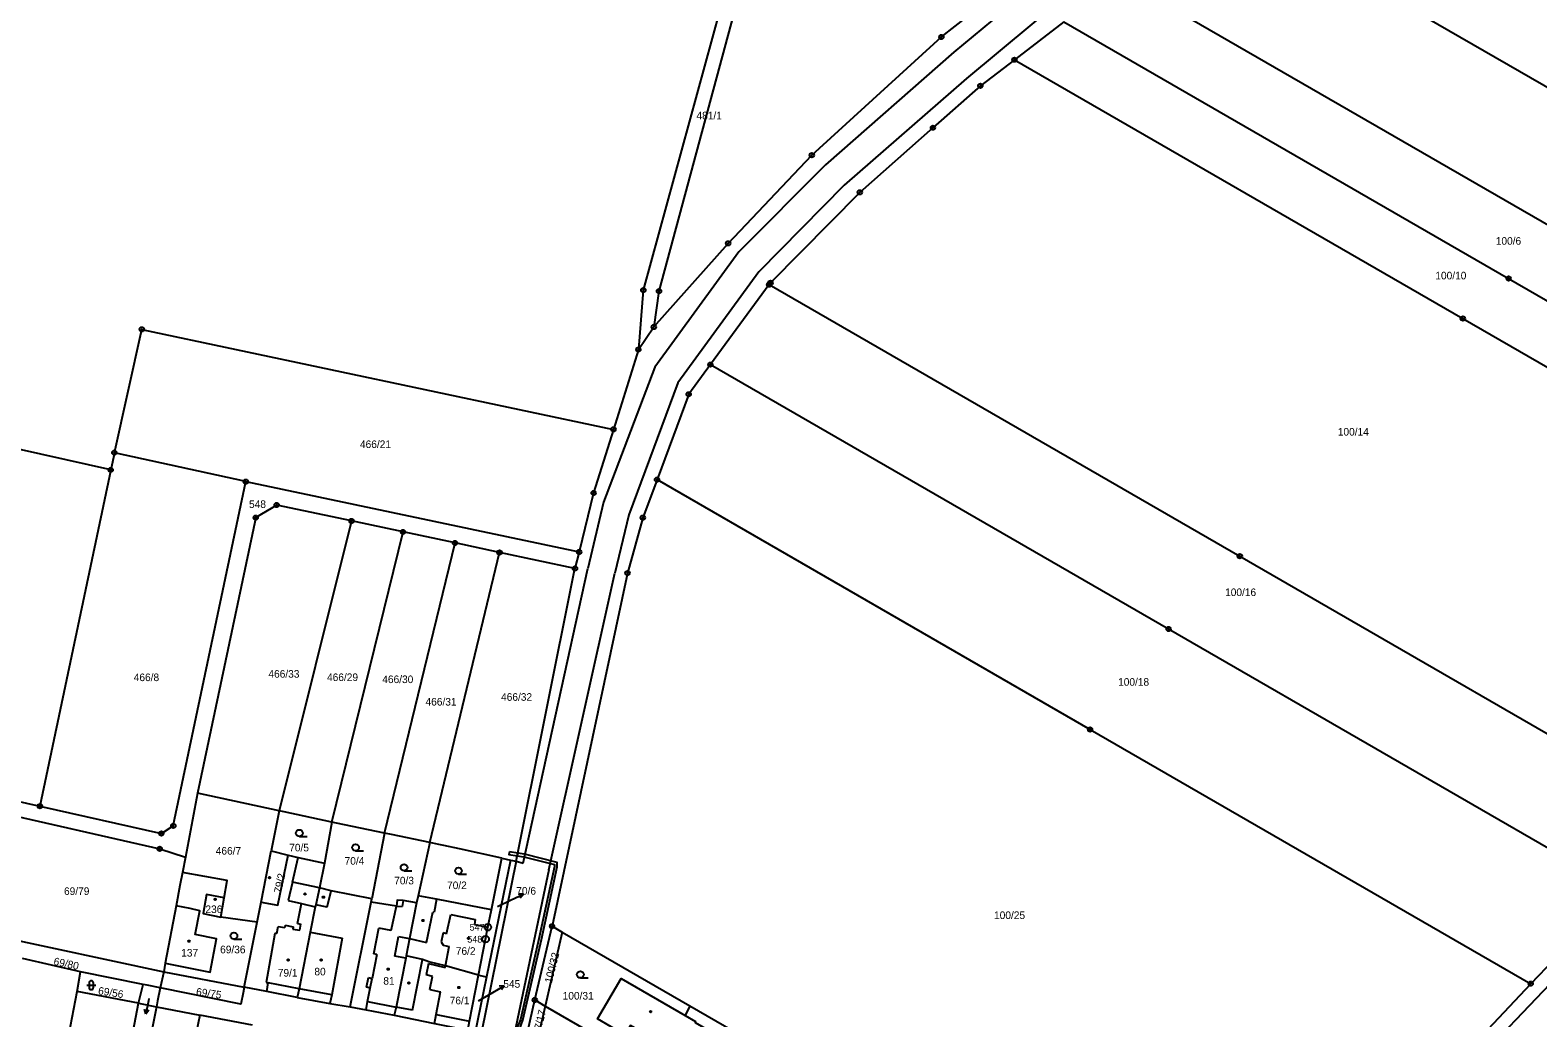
# Model space of a CAD drawing. Extents: x -758582 to -751794, y -998770 to -994350.
# Drawn here: x -756555.4 to -756217.6, y -996694.2 to -996472.9 of the extents above; entities that cross this region are included whole.
import ezdxf

# ---------------------------------------------------------------- set-up
doc = ezdxf.new("R2010")
doc.units = 0
for name, color, linetype in [('Hranice parcel', 7, 'Continuous'), ('Parcelní čísla', 7, 'Continuous'), ('Pop  PČ popisy', 7, 'Continuous'), ('Vnitřní kresba', 7, 'Continuous'), ('Věcná břemena k části', 7, 'Continuous'), ('Značky bodu BP', 7, 'Continuous'), ('Značky budov', 7, 'Continuous'), ('Značky kultur', 7, 'Continuous')]:
    doc.layers.add(name, color=color, linetype=linetype)

msp = doc.modelspace()

# ---------------------------------------------------------------- linework, layer by layer
at = {"layer": 'Hranice parcel'}
for p, q in [((-756323.8, -996471.09), (-756334.9, -996479.57)), ((-756389.84, -996529.96), (-756403, -996547.87)), ((-756419.13, -996544.5), (-756415.69, -996539.44)), ((-756419.13, -996544.5), (-756424.72, -996562.38)), ((-756537.34, -996571.47), (-756637.67, -996548.94)), ((-756536.53, -996567.61), (-756537.34, -996571.47)), ((-756507.07, -996574.09), (-756536.53, -996567.61)), ((-756537.34, -996571.47), (-756553.21, -996646.8)), ((-756507.07, -996574.09), (-756432.41, -996589.85)), ((-756483.39, -996582.91), (-756499.58, -996647.83)), ((-756471.85, -996585.36), (-756483.39, -996582.91)), ((-756487.79, -996650.37), (-756471.85, -996585.36)), ((-756476, -996652.82), (-756460.21, -996587.84)), ((-756460.21, -996587.84), (-756471.85, -996585.36)), ((-756450.24, -996589.96), (-756460.21, -996587.84)), ((-756465.85, -996654.97), (-756450.24, -996589.96)), ((-756433.34, -996593.55), (-756450.24, -996589.96)), ((-756432.41, -996589.85), (-756433.34, -996593.55)), ((-756517.93, -996643.88), (-756520.63, -996658.26)), ((-756499.58, -996647.83), (-756517.93, -996643.88)), ((-756499.58, -996647.83), (-756501.39, -996656.8)), ((-756487.79, -996650.37), (-756489.42, -996659.57)), ((-756476, -996652.82), (-756478.88, -996667.6)), ((-756465.85, -996654.97), (-756468.48, -996666.87)), ((-756520.63, -996658.26), (-756521.29, -996661.68)), ((-756503.67, -996668.3), (-756501.39, -996656.8)), ((-756501.39, -996656.8), (-756497.63, -996657.75)), ((-756452.05, -996670.06), (-756449.69, -996658.43)), ((-756449.69, -996658.43), (-756447.79, -996658.87)), ((-756489.42, -996659.57), (-756490.55, -996665.12)), ((-756447.79, -996658.87), (-756453.14, -996685.02)), ((-756512.69, -996671.64), (-756511.93, -996667.35)), ((-756504.57, -996672.81), (-756503.67, -996668.3)), ((-756483.74, -996691.75), (-756478.99, -996668.33)), ((-756478.99, -996668.33), (-756478.88, -996667.6)), ((-756468.48, -996666.87), (-756468.85, -996668.5)), ((-756522.7, -996669.14), (-756525.17, -996681.96)), ((-756504.57, -996672.81), (-756512.69, -996671.64)), ((-756571.21, -996674.08), (-756525.43, -996683.94)), ((-756507.45, -996687.39), (-756504.57, -996672.81)), ((-756442.34, -996690.23), (-756438.47, -996673.71)), ((-756436.2, -996675.02), (-756440, -996691.58)), ((-756438.47, -996673.71), (-756436.2, -996675.02)), ((-756436.2, -996675.02), (-756407.63, -996691.51)), ((-756544.1, -996683.91), (-756557.08, -996680.97)), ((-756525.17, -996681.96), (-756525.43, -996683.94)), ((-756544.86, -996688.3), (-756544.1, -996683.91)), ((-756530.11, -996686.75), (-756544.1, -996683.91)), ((-756525.43, -996683.94), (-756526.24, -996687.53)), ((-756525.43, -996683.94), (-756507.45, -996687.39)), ((-756453.14, -996685.02), (-756455.83, -996698.22)), ((-756454.96, -996684.65), (-756453.14, -996685.02)), ((-756549.87, -996714.27), (-756544.86, -996688.3)), ((-756531.1, -996690.92), (-756544.86, -996688.3)), ((-756531.1, -996690.92), (-756530.11, -996686.75)), ((-756536.42, -996718.33), (-756531.1, -996690.92)), ((-756531.1, -996690.92), (-756527.09, -996691.75)), ((-756527.09, -996691.75), (-756528.96, -996701.04)), ((-756527.09, -996691.75), (-756517.41, -996693.6)), ((-756444.45, -996699.47), (-756442.34, -996690.23)), ((-756442.34, -996690.23), (-756440, -996691.58)), ((-756440, -996691.58), (-756441.94, -996700.02)), ((-756440, -996691.58), (-756418.49, -996704)), ((-756407.63, -996691.51), (-756408.66, -996693.68)), ((-756407.63, -996691.51), (-756383.48, -996705.44)), ((-756505.62, -996695.91), (-756517.41, -996693.6))]:
    msp.add_line(p, q, dxfattribs=at)
for points in [[(-756352.76, -996200.65), (-756349.8, -996238.04), (-756346.39, -996274.67), (-756346.28, -996291.38), (-756349.04, -996311.87), (-756358.8, -996347.7), (-756380.64, -996409.93), (-756400.89, -996468.48), (-756418.03, -996531.2), (-756419.13, -996544.5)], [(-756358.49, -996358.56), (-756377.3, -996411), (-756397.84, -996469.46), (-756414.53, -996531.41), (-756415.69, -996539.44)], [(-756415.69, -996539.44), (-756399.01, -996520.7), (-756380.29, -996500.96), (-756351.25, -996474.46), (-756305.28, -996438.52), (-756260.4, -996403.06), (-756238.56, -996389.57)], [(-756289.97, -996442.74), (-756195.56, -996497.21), (-756100.21, -996552.23)], [(-756311.7, -996460.95), (-756214.69, -996516.92), (-756116.22, -996573.74)], [(-756323.8, -996471.09), (-756224.19, -996528.57), (-756125.14, -996585.72)], [(-756334.9, -996479.57), (-756342.53, -996485.4), (-756353.15, -996494.8), (-756369.52, -996509.28), (-756389.54, -996529.55), (-756389.84, -996529.96)], [(-756334.9, -996479.57), (-756234.43, -996537.55), (-756132.9, -996596.13)], [(-756389.84, -996529.96), (-756284.41, -996590.79), (-756179.61, -996651.27)], [(-756536.53, -996567.61), (-756530.38, -996539.97), (-756424.72, -996562.38)], [(-756403, -996547.87), (-756407.87, -996554.51), (-756414.96, -996573.64)], [(-756403, -996547.87), (-756300.36, -996607.1), (-756196.89, -996666.8)], [(-756424.72, -996562.38), (-756429.17, -996576.63), (-756432.41, -996589.85)], [(-756553.21, -996646.8), (-756525.99, -996652.92), (-756523.33, -996651.21), (-756507.07, -996574.09)], [(-756414.96, -996573.64), (-756418.13, -996582.17), (-756421.57, -996594.58), (-756438.47, -996673.71)], [(-756414.96, -996573.64), (-756317.95, -996629.62), (-756219.23, -996686.58)], [(-756483.39, -996582.91), (-756500.17, -996579.34), (-756504.86, -996582.16), (-756517.93, -996643.88)], [(-756447.79, -996658.87), (-756446.55, -996659.16), (-756433.34, -996593.55)], [(-756653.54, -996624.22), (-756630.99, -996629.3), (-756553.21, -996646.8)], [(-756565.19, -996647.53), (-756526.37, -996656.37), (-756520.63, -996658.26)], [(-756487.79, -996650.37), (-756498.47, -996648.07), (-756499.58, -996647.83)], [(-756476, -996652.82), (-756486.76, -996650.58), (-756487.79, -996650.37)], [(-756465.85, -996654.97), (-756474.42, -996653.15), (-756476, -996652.82)], [(-756449.69, -996658.43), (-756459.24, -996656.39), (-756462.73, -996655.64), (-756463.5, -996655.47), (-756463.87, -996655.39), (-756465.85, -996654.97)], [(-756503.67, -996668.3), (-756499.94, -996669.02), (-756497.63, -996657.75)], [(-756497.63, -996657.75), (-756495.33, -996658.31), (-756489.42, -996659.57)], [(-756521.29, -996661.68), (-756521.85, -996664.55), (-756522.7, -996669.14)], [(-756511.93, -996667.35), (-756511.28, -996663.43), (-756521.29, -996661.68)], [(-756182.87, -996659.09), (-756211.86, -996683.49), (-756234.83, -996707.54), (-756253.45, -996735.72), (-756269.43, -996768.85), (-756277.38, -996793.04)], [(-756490.55, -996665.12), (-756491.4, -996668.89), (-756491.57, -996669.33), (-756492.66, -996675.04), (-756495.16, -996687.72), (-756495.56, -996689.66)], [(-756478.88, -996667.6), (-756487.94, -996665.8), (-756490.55, -996665.12)], [(-756511.93, -996667.35), (-756515.89, -996666.63), (-756516.66, -996670.84), (-756512.69, -996671.64)], [(-756468.85, -996668.5), (-756471.81, -996667.97), (-756473.17, -996667.85), (-756473.35, -996669.22), (-756478.99, -996668.33)], [(-756468.85, -996668.5), (-756470.4, -996676.49), (-756471.13, -996680.37)], [(-756452.05, -996670.06), (-756464.34, -996667.63), (-756468.48, -996666.87)], [(-756219.23, -996686.58), (-756213.87, -996681.09), (-756196.89, -996666.8)], [(-756525.17, -996681.96), (-756515.08, -996684), (-756513.65, -996676.52), (-756518.42, -996675.58), (-756517.35, -996670.23), (-756519.57, -996669.71), (-756522.7, -996669.14)], [(-756454.96, -996684.65), (-756453.36, -996676.62), (-756452.85, -996673.94), (-756452.05, -996670.06)], [(-756471.13, -996680.37), (-756471.22, -996680.85), (-756473.42, -996691.82), (-756473.84, -996693.67)], [(-756454.96, -996684.65), (-756462.35, -996682.57), (-756466.07, -996681.7), (-756467.51, -996681.13), (-756471.13, -996680.37)], [(-756457.34, -996696.98), (-756456.95, -996695), (-756454.96, -996684.65)], [(-756418.49, -996704), (-756415.62, -996699.01), (-756420.88, -996695.92), (-756422.14, -996698.06), (-756428.32, -996694.47), (-756423.03, -996685.4), (-756408.66, -996693.68)], [(-756526.24, -996687.53), (-756529.15, -996686.94), (-756530.11, -996686.75)], [(-756526.24, -996687.53), (-756526.9, -996690.44), (-756527.09, -996691.75)], [(-756507.45, -996687.39), (-756507.7, -996688.64), (-756508.22, -996691.18), (-756526.24, -996687.53)], [(-756495.56, -996689.66), (-756502.4, -996688.35), (-756507.45, -996687.39)], [(-756272.78, -996769.33), (-756272.31, -996767.73), (-756256.4, -996734.07), (-756237.24, -996705.72), (-756219.23, -996686.58)], [(-756495.56, -996689.66), (-756488.27, -996691.04), (-756483.74, -996691.75)], [(-756483.74, -996691.75), (-756480.1, -996692.44), (-756473.84, -996693.67)], [(-756517.41, -996693.6), (-756517.79, -996695.43), (-756519.19, -996702.61)], [(-756473.84, -996693.67), (-756464.79, -996695.51), (-756457.34, -996696.98)], [(-756408.66, -996693.68), (-756406.32, -996695.03), (-756406.45, -996695.26), (-756401.25, -996698.26), (-756405, -996704.68), (-756410.17, -996701.69), (-756413.25, -996707.02)]]:
    msp.add_lwpolyline(points, dxfattribs=at)
at = {"layer": 'Pop  PČ popisy'}
for p, q in [((-756450.73, -996669.26), (-756447.62, -996667.81)), ((-756447.62, -996667.81), (-756444.9, -996666.54)), ((-756444.9, -996666.54), (-756446.02, -996666.51)), ((-756444.9, -996666.54), (-756445.6, -996667.42)), ((-756454.99, -996690.41), (-756451.77, -996688.53)), ((-756451.77, -996688.53), (-756449.17, -996687.03)), ((-756449.17, -996687.03), (-756450.29, -996687.1)), ((-756449.17, -996687.03), (-756449.79, -996687.96)), ((-756529.48, -996693.34), (-756529.78, -996692.26)), ((-756528.91, -996690.39), (-756529.48, -996693.34)), ((-756529.48, -996693.34), (-756528.8, -996692.45)), ((-756528.81, -996689.91), (-756528.91, -996690.39))]:
    msp.add_line(p, q, dxfattribs=at)
at = {"layer": 'Vnitřní kresba'}
for p, q in [((-756303.94, -996440.94), (-756348.49, -996477.86)), ((-756299.76, -996445.56), (-756345.66, -996483.74)), ((-756348.49, -996477.86), (-756377.25, -996503.09)), ((-756345.66, -996483.74), (-756373.01, -996507.69)), ((-756377.25, -996503.09), (-756396.64, -996522.6)), ((-756373.01, -996507.69), (-756392.14, -996527.05)), ((-756396.64, -996522.6), (-756415.43, -996548.48)), ((-756392.14, -996527.05), (-756410.29, -996551.98)), ((-756415.43, -996548.48), (-756426.94, -996578.69)), ((-756410.29, -996551.98), (-756421.27, -996581.56)), ((-756426.94, -996578.69), (-756430.48, -996593.57)), ((-756421.27, -996581.56), (-756424.4, -996594.61)), ((-756444.97, -996659.57), (-756430.48, -996593.57)), ((-756439.22, -996661.07), (-756424.4, -996594.61)), ((-756496.63, -996663.8), (-756495.33, -996658.31)), ((-756446.55, -996659.16), (-756454.27, -996697.45)), ((-756439.22, -996661.07), (-756449.71, -996710.99)), ((-756446.55, -996659.16), (-756444.97, -996659.57)), ((-756496.63, -996663.8), (-756497.57, -996667.93)), ((-756490.55, -996665.12), (-756496.63, -996663.8)), ((-756497.57, -996667.93), (-756494.63, -996668.65)), ((-756495.53, -996673.12), (-756494.63, -996668.65)), ((-756494.63, -996668.65), (-756491.57, -996669.33)), ((-756488.83, -996669.47), (-756491.4, -996668.89)), ((-756488.83, -996669.47), (-756487.94, -996665.8)), ((-756471.81, -996667.97), (-756472.05, -996669.31)), ((-756464.34, -996667.63), (-756464.91, -996670.59)), ((-756474.53, -996674.65), (-756473.35, -996669.22)), ((-756473.35, -996669.22), (-756472.05, -996669.31)), ((-756466.57, -996677.34), (-756465.2, -996670.54)), ((-756465.2, -996670.54), (-756464.91, -996670.59)), ((-756462.09, -996675.39), (-756461.16, -996671.05)), ((-756461.16, -996671.05), (-756455.69, -996672.18)), ((-756455.69, -996672.18), (-756455.83, -996673.31)), ((-756500.57, -996675.31), (-756502.55, -996686.31)), ((-756500.13, -996675.35), (-756500.57, -996675.31)), ((-756500.13, -996675.35), (-756499.81, -996673.76)), ((-756499.81, -996673.76), (-756498.35, -996673.98)), ((-756498.23, -996673.46), (-756498.35, -996673.98)), ((-756498.23, -996673.46), (-756496.45, -996673.82)), ((-756496.45, -996673.82), (-756496.58, -996674.33)), ((-756496.58, -996674.33), (-756494.97, -996674.62)), ((-756495.53, -996673.12), (-756494.72, -996673.22)), ((-756494.97, -996674.62), (-756494.72, -996673.22)), ((-756492.66, -996675.04), (-756485.52, -996676.39)), ((-756478.39, -996679.87), (-756477.31, -996674.15)), ((-756474.53, -996674.65), (-756477.31, -996674.15)), ((-756462.9, -996675.22), (-756463.31, -996677.18)), ((-756462.09, -996675.39), (-756462.9, -996675.22)), ((-756455.83, -996673.31), (-756452.85, -996673.94)), ((-756485.52, -996676.39), (-756487.82, -996689.07)), ((-756473.68, -996680.39), (-756472.87, -996676.03)), ((-756472.87, -996676.03), (-756470.4, -996676.49)), ((-756470.4, -996676.49), (-756466.57, -996677.34)), ((-756463.31, -996677.18), (-756462.86, -996677.97)), ((-756462.86, -996677.97), (-756461.51, -996678.28)), ((-756462.35, -996682.57), (-756461.51, -996678.28)), ((-756477.71, -996680.01), (-756478.79, -996685.39)), ((-756477.71, -996680.01), (-756478.39, -996679.87)), ((-756471.22, -996680.85), (-756473.68, -996680.39)), ((-756469.75, -996692.55), (-756467.51, -996681.13)), ((-756466.15, -996682.05), (-756466.71, -996684.6)), ((-756466.15, -996682.05), (-756462.43, -996682.95)), ((-756480.02, -996687.39), (-756479.58, -996685.22)), ((-756479.58, -996685.22), (-756478.79, -996685.39)), ((-756479.22, -996687.55), (-756478.79, -996685.39)), ((-756465.27, -996684.94), (-756466.71, -996684.6)), ((-756465.87, -996687.9), (-756465.27, -996684.94)), ((-756462.43, -996682.95), (-756462.35, -996682.57)), ((-756502.55, -996686.31), (-756502.06, -996686.39)), ((-756502.4, -996688.35), (-756502.06, -996686.39)), ((-756495.16, -996687.72), (-756502.06, -996686.39)), ((-756487.82, -996689.07), (-756495.16, -996687.72)), ((-756487.82, -996689.07), (-756488.27, -996691.04)), ((-756479.22, -996687.55), (-756480.02, -996687.39)), ((-756479.79, -996690.59), (-756479.22, -996687.55)), ((-756465.87, -996687.9), (-756463.49, -996688.41)), ((-756464.46, -996693.5), (-756463.49, -996688.41)), ((-756480.1, -996692.44), (-756479.79, -996690.59)), ((-756479.79, -996690.59), (-756473.42, -996691.82)), ((-756469.75, -996692.55), (-756473.42, -996691.82)), ((-756464.79, -996695.51), (-756464.46, -996693.5)), ((-756464.46, -996693.5), (-756456.95, -996695))]:
    msp.add_line(p, q, dxfattribs=at)
at = {"layer": 'Věcná břemena k části'}
for points in [[(-756447.99, -996657.07), (-756448.14, -996657.66), (-756446.3, -996657.92), (-756446.18, -996657.33)], [(-756444.78, -996658.13), (-756437.93, -996659.88), (-756437.92, -996660.31), (-756441.45, -996676.56), (-756445.57, -996694.6), (-756446.33, -996696.6), (-756446.9, -996697.86), (-756446.7, -996699.37), (-756445.76, -996700.18), (-756444.76, -996700.83), (-756444.62, -996700.21), (-756445.4, -996699.7), (-756446.14, -996699.07), (-756446.28, -996697.96), (-756445.77, -996696.84), (-756444.99, -996694.78), (-756440.87, -996676.7), (-756437.32, -996660.37), (-756437.35, -996659.42), (-756444.66, -996657.55), (-756446.18, -996657.33), (-756446.3, -996657.92)]]:
    msp.add_lwpolyline(points, close=True, dxfattribs=at)
at = {"layer": 'Značky bodu BP'}
for centre, radius in [((-756351.25, -996474.46), 0.5), ((-756351.25, -996474.46), 0.0303), ((-756334.9, -996479.57), 0.5), ((-756334.9, -996479.57), 0.0303), ((-756342.53, -996485.4), 0.5), ((-756342.53, -996485.4), 0.0303), ((-756353.15, -996494.8), 0.5), ((-756353.15, -996494.8), 0.0303), ((-756380.29, -996500.96), 0.5), ((-756380.29, -996500.96), 0.0303), ((-756369.52, -996509.28), 0.5), ((-756369.52, -996509.28), 0.0303), ((-756399.01, -996520.7), 0.5), ((-756399.01, -996520.7), 0.0303), ((-756389.84, -996529.96), 0.5), ((-756389.54, -996529.55), 0.5), ((-756389.84, -996529.96), 0.0303), ((-756389.54, -996529.55), 0.0303), ((-756224.19, -996528.57), 0.5), ((-756224.19, -996528.57), 0.0303), ((-756418.03, -996531.2), 0.5), ((-756418.03, -996531.2), 0.0303), ((-756414.53, -996531.41), 0.5), ((-756414.53, -996531.41), 0.0303), ((-756234.43, -996537.55), 0.5), ((-756530.38, -996539.97), 0.5), ((-756530.38, -996539.97), 0.0303), ((-756415.69, -996539.44), 0.5), ((-756415.69, -996539.44), 0.0303), ((-756234.43, -996537.55), 0.0303), ((-756419.13, -996544.5), 0.5), ((-756419.13, -996544.5), 0.0303), ((-756403, -996547.87), 0.5), ((-756403, -996547.87), 0.0303), ((-756407.87, -996554.51), 0.5), ((-756407.87, -996554.51), 0.0303), ((-756424.72, -996562.38), 0.5), ((-756424.72, -996562.38), 0.0303), ((-756536.53, -996567.61), 0.5), ((-756536.53, -996567.61), 0.0303), ((-756537.34, -996571.47), 0.5), ((-756537.34, -996571.47), 0.0303), ((-756507.07, -996574.09), 0.5), ((-756507.07, -996574.09), 0.0303), ((-756414.96, -996573.64), 0.5), ((-756414.96, -996573.64), 0.0303), ((-756429.17, -996576.63), 0.5), ((-756429.17, -996576.63), 0.0303), ((-756500.17, -996579.34), 0.5), ((-756500.17, -996579.34), 0.0303), ((-756504.86, -996582.16), 0.5), ((-756504.86, -996582.16), 0.0303), ((-756483.39, -996582.91), 0.5), ((-756483.39, -996582.91), 0.0303), ((-756418.13, -996582.17), 0.5), ((-756418.13, -996582.17), 0.0303), ((-756471.85, -996585.36), 0.5), ((-756471.85, -996585.36), 0.0303), ((-756460.21, -996587.84), 0.5), ((-756460.21, -996587.84), 0.0303), ((-756450.24, -996589.96), 0.5), ((-756450.24, -996589.96), 0.0303), ((-756432.41, -996589.85), 0.5), ((-756432.41, -996589.85), 0.0303), ((-756284.41, -996590.79), 0.5), ((-756284.41, -996590.79), 0.0303), ((-756433.34, -996593.55), 0.5), ((-756433.34, -996593.55), 0.0303), ((-756421.57, -996594.58), 0.5), ((-756421.57, -996594.58), 0.0303), ((-756300.36, -996607.1), 0.5), ((-756300.36, -996607.1), 0.0303), ((-756317.95, -996629.62), 0.5), ((-756317.95, -996629.62), 0.0303), ((-756553.21, -996646.8), 0.5), ((-756553.21, -996646.8), 0.0303), ((-756523.33, -996651.21), 0.5), ((-756523.33, -996651.21), 0.0303), ((-756525.99, -996652.92), 0.5), ((-756525.99, -996652.92), 0.0303), ((-756526.37, -996656.37), 0.5), ((-756526.37, -996656.37), 0.0303), ((-756452.85, -996673.94), 0.75), ((-756452.85, -996673.94), 0.03), ((-756438.47, -996673.71), 0.5), ((-756438.47, -996673.71), 0.0303), ((-756453.36, -996676.62), 0.75), ((-756453.36, -996676.62), 0.03), ((-756219.23, -996686.58), 0.5), ((-756219.23, -996686.58), 0.0303), ((-756442.34, -996690.23), 0.5), ((-756442.34, -996690.23), 0.0303)]:
    msp.add_circle(centre, radius, dxfattribs=at)
at = {"layer": 'Značky budov'}
for centre in [(-756501.78, -996662.83), (-756513.94, -996667.7), (-756493.8, -996666.47), (-756489.69, -996667.19), (-756467.38, -996672.43), (-756519.8, -996677.06), (-756457.2, -996676.44), (-756497.6, -996681.27), (-756490.2, -996681.27), (-756475.19, -996683.33), (-756470.57, -996686.42), (-756459.36, -996687.44), (-756416.37, -996692.85)]:
    msp.add_circle(centre, 0.175, dxfattribs=at)
at = {"layer": 'Značky kultur'}
for p, q in [((-756495.09, -996653.58), (-756493.34, -996653.58)), ((-756482.48, -996656.83), (-756480.73, -996656.83)), ((-756471.64, -996661.28), (-756469.89, -996661.28)), ((-756459.43, -996662.05), (-756457.68, -996662.05)), ((-756509.74, -996676.6), (-756507.99, -996676.6)), ((-756432.14, -996685.3), (-756430.39, -996685.3)), ((-756542.71, -996686.92), (-756540.71, -996686.92)), ((-756542.21, -996686.42), (-756542.21, -996687.42)), ((-756541.21, -996687.42), (-756541.21, -996686.42))]:
    msp.add_line(p, q, dxfattribs=at)
for centre in [(-756495.09, -996652.83), (-756482.48, -996656.08), (-756471.64, -996660.53), (-756459.43, -996661.3), (-756509.74, -996675.85), (-756432.14, -996684.55)]:
    msp.add_circle(centre, 0.75, dxfattribs=at)
for centre, start, end in [((-756541.71, -996686.42), 0, 180), ((-756541.71, -996687.42), 180, 359.9879)]:
    msp.add_arc(centre, 0.5, start, end, dxfattribs=at)

# ---------------------------------------------------------------- texts
at = {"layer": 'Parcelní čísla'}
for s, p in [('481/1', (-756406.12, -996492.92)), ('100/6', (-756227.06, -996521.01)), ('100/10', (-756240.6, -996528.77)), ('100/14', (-756262.45, -996563.78)), ('466/21', (-756481.51, -996566.56)), ('548', (-756506.36, -996579.99)), ('100/16', (-756287.7, -996599.73)), ('466/8', (-756532.19, -996618.79)), ('466/33', (-756502.02, -996618.02)), ('466/29', (-756488.89, -996618.77)), ('466/30', (-756476.51, -996619.23)), ('100/18', (-756311.67, -996619.82)), ('466/32', (-756449.9, -996623.19)), ('466/31', (-756466.82, -996624.26)), ('70/5', (-756497.36, -996656.94)), ('466/7', (-756513.82, -996657.66)), ('70/4', (-756484.95, -996659.91)), ('69/79', (-756547.81, -996666.7)), ('70/3', (-756473.84, -996664.33)), ('70/2', (-756462, -996665.39)), ('70/6', (-756446.49, -996666.63)), ('236', (-756516.13, -996670.75)), ('100/25', (-756339.46, -996672.09)), ('137', (-756521.56, -996680.51)), ('69/36', (-756512.84, -996679.77)), ('76/2', (-756460.04, -996680.11)), ('79/1', (-756499.92, -996684.99)), ('80', (-756491.72, -996684.72)), ('81', (-756476.28, -996686.8)), ('545', (-756449.4, -996687.49)), ('100/31', (-756436.1, -996690.14)), ('76/1', (-756461.41, -996691.2))]:
    msp.add_text(s, height=1.7, dxfattribs=at).set_placement(p)
for s, rotation, p in [('79/2', 78, (-756499.13, -996666.4)), ('69/80', 348, (-756550.26, -996682.33)), ('100/32', 76, (-756438.52, -996686.58)), ('69/56', 351, (-756540.26, -996688.94)), ('69/75', 352, (-756518.3, -996689.17)), ('107/17', 76, (-756441.48, -996699.45))]:
    msp.add_text(s, height=1.7, rotation=rotation, dxfattribs=at).set_placement(p)
at = {"layer": 'Značky bodu BP'}
for s, p in [('547', (-756456.95, -996674.69)), ('548', (-756457.46, -996677.37))]:
    msp.add_text(s, height=1.5, dxfattribs=at).set_placement(p)

doc.saveas('drawing.dxf')
